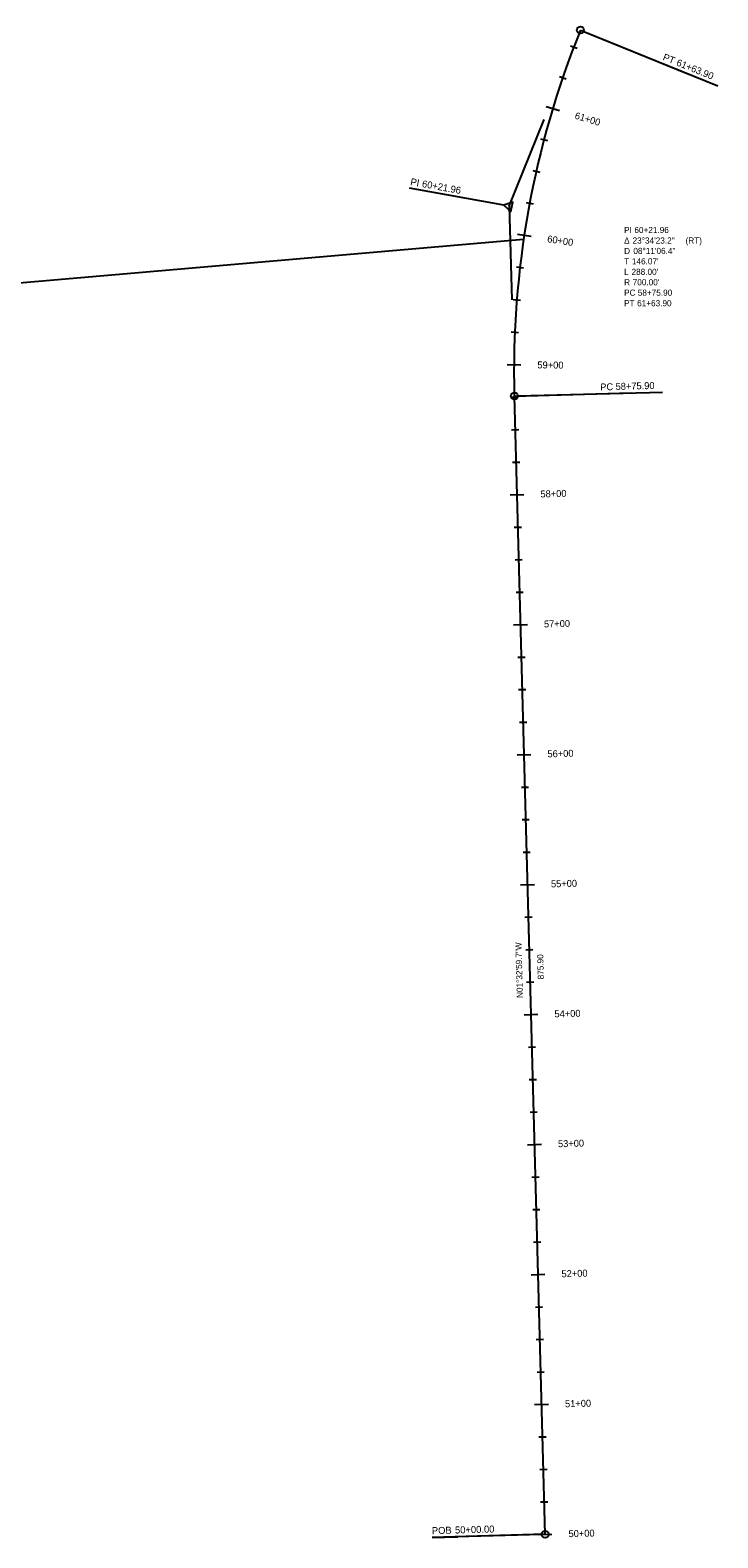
# Model space of a CAD drawing. Extents: x 2307903 to 2339201, y 758183 to 762824.
# Drawn here: x 2320206 to 2320735, y 758183 to 759343 of the extents above; entities that cross this region are included whole.
import ezdxf

# ---------------------------------------------------------------- set-up
doc = ezdxf.new("R2010")
doc.units = 0
for name, color, linetype in [('Default', 7, 'Continuous'), ('E_Terrain_Contour_Imported', 7, 'Continuous'), ('E_Terrain_Contour_Major', 7, 'Continuous'), ('E_Terrain_Flow_Arrows', 7, 'Continuous'), ('E_Terrain_Island', 7, 'Continuous'), ('E_Terrain_Points_High', 7, 'Continuous'), ('E_Terrain_Points_Low', 7, 'Continuous'), ('E_Terrain_SpotElevation', 7, 'Continuous'), ('Geom_Baseline', 7, 'Continuous')]:
    doc.layers.add(name, color=color, linetype=linetype)

msp = doc.modelspace()

# ---------------------------------------------------------------- linework, layer by layer
at = {"layer": 'Default'}
for p, q in [((2320621.7, 759331.1), (2320626.9, 759329.1)), ((2320613.2, 759307.5), (2320618.4, 759305.7)), ((2320603.1, 759284.4), (2320613.2, 759281.3)), ((2320598.7, 759259.5), (2320604, 759258.1)), ((2320592.8, 759235.1), (2320598.1, 759233.9)), ((2320587.7, 759210.5), (2320593.1, 759209.5)), ((2320580.9, 759186.1), (2320591.4, 759184.6)), ((2320580.2, 759160.9), (2320585.6, 759160.3)), ((2320577.7, 759135.9), (2320583.2, 759135.5)), ((2320576.2, 759110.9), (2320581.7, 759110.6)), ((2320573, 759085.8), (2320583.6, 759085.7)), ((2320602.3, 758186.1), (2320578.6, 759061.6)), ((2320602.3, 758186.1), (2320578.6, 759061.6)), ((2320602.3, 758186.1), (2320578.6, 759061.6)), ((2320602.3, 758186.1), (2320578.6, 759061.6)), ((2320575.8, 759060.7), (2320581.4, 759060.8)), ((2320576.5, 759035.7), (2320582, 759035.8)), ((2320577.2, 759010.7), (2320582.7, 759010.8)), ((2320575.3, 758985.6), (2320585.9, 758985.9)), ((2320578.5, 758960.7), (2320584.1, 758960.9)), ((2320579.2, 758935.7), (2320584.7, 758935.9)), ((2320579.9, 758910.7), (2320585.4, 758910.9)), ((2320578, 758885.7), (2320588.6, 758886)), ((2320581.2, 758860.7), (2320586.8, 758860.9)), ((2320581.9, 758835.8), (2320587.4, 758835.9)), ((2320582.6, 758810.8), (2320588.1, 758810.9)), ((2320580.7, 758785.7), (2320591.3, 758786)), ((2320584, 758760.8), (2320589.5, 758760.9)), ((2320584.6, 758735.8), (2320590.1, 758735.9)), ((2320585.3, 758710.8), (2320590.8, 758710.9)), ((2320583.4, 758685.7), (2320594, 758686)), ((2320586.7, 758660.8), (2320592.2, 758661)), ((2320587.3, 758635.8), (2320592.9, 758636)), ((2320588, 758610.8), (2320593.5, 758611)), ((2320586.1, 758585.8), (2320596.7, 758586.1)), ((2320589.4, 758560.9), (2320594.9, 758561)), ((2320590, 758535.9), (2320595.6, 758536)), ((2320590.7, 758510.9), (2320596.2, 758511)), ((2320588.8, 758485.8), (2320599.4, 758486.1)), ((2320592.1, 758460.9), (2320597.6, 758461)), ((2320592.7, 758435.9), (2320598.3, 758436)), ((2320593.4, 758410.9), (2320598.9, 758411.1)), ((2320591.5, 758385.8), (2320602.1, 758386.1)), ((2320594.8, 758360.9), (2320600.3, 758361.1)), ((2320595.4, 758335.9), (2320601, 758336.1)), ((2320596.1, 758310.9), (2320601.6, 758311.1)), ((2320594.2, 758285.9), (2320604.8, 758286.2)), ((2320597.5, 758261), (2320603, 758261.1)), ((2320598.2, 758236), (2320603.7, 758236.1)), ((2320598.8, 758211), (2320604.3, 758211.1)), ((2320596.9, 758185.9), (2320607.5, 758186.2))]:
    msp.add_line(p, q, dxfattribs=at)
msp.add_arc((2321278.3, 759080.6), 700, 157.9768, 181.5499, dxfattribs=at)
msp.add_arc((2321278.3, 759080.6), 700, 157.9768, 181.5499, dxfattribs=at)
msp.add_arc((2321278.3, 759080.6), 700, 157.9768, 181.5499, dxfattribs=at)
msp.add_arc((2321278.3, 759080.6), 700, 157.9768, 181.5499, dxfattribs=at)
msp.add_arc((2321278.3, 759080.6), 700, 157.9768, 181.5499, dxfattribs=at)
at = {"layer": 'E_Terrain_Contour_Imported'}
for p, q in [((2320621.7, 759331.1), (2320626.9, 759329.1)), ((2320613.2, 759307.5), (2320618.4, 759305.7)), ((2320598.7, 759259.5), (2320604, 759258.1)), ((2320592.8, 759235.1), (2320598.1, 759233.9)), ((2320587.7, 759210.5), (2320593.1, 759209.5)), ((2320580.2, 759160.9), (2320585.6, 759160.3)), ((2320577.7, 759135.9), (2320583.2, 759135.5)), ((2320576.2, 759110.9), (2320581.7, 759110.6)), ((2320575.8, 759060.7), (2320581.4, 759060.8)), ((2320576.5, 759035.7), (2320582, 759035.8)), ((2320577.2, 759010.7), (2320582.7, 759010.8)), ((2320578.5, 758960.7), (2320584.1, 758960.9)), ((2320579.2, 758935.7), (2320584.7, 758935.9)), ((2320579.9, 758910.7), (2320585.4, 758910.9)), ((2320581.2, 758860.7), (2320586.8, 758860.9)), ((2320581.9, 758835.8), (2320587.4, 758835.9)), ((2320582.6, 758810.8), (2320588.1, 758810.9)), ((2320584, 758760.8), (2320589.5, 758760.9)), ((2320584.6, 758735.8), (2320590.1, 758735.9)), ((2320585.3, 758710.8), (2320590.8, 758710.9)), ((2320586.7, 758660.8), (2320592.2, 758661)), ((2320587.3, 758635.8), (2320592.9, 758636)), ((2320588, 758610.8), (2320593.5, 758611)), ((2320589.4, 758560.9), (2320594.9, 758561)), ((2320590, 758535.9), (2320595.6, 758536)), ((2320590.7, 758510.9), (2320596.2, 758511)), ((2320592.1, 758460.9), (2320597.6, 758461)), ((2320592.7, 758435.9), (2320598.3, 758436)), ((2320593.4, 758410.9), (2320598.9, 758411.1)), ((2320594.8, 758360.9), (2320600.3, 758361.1)), ((2320595.4, 758335.9), (2320601, 758336.1)), ((2320596.1, 758310.9), (2320601.6, 758311.1)), ((2320597.5, 758261), (2320603, 758261.1)), ((2320598.2, 758236), (2320603.7, 758236.1)), ((2320598.8, 758211), (2320604.3, 758211.1))]:
    msp.add_line(p, q, dxfattribs=at)
at = {"layer": 'E_Terrain_Island'}
for p, q in [((2320603.1, 759284.4), (2320613.2, 759281.3)), ((2320580.9, 759186.1), (2320591.4, 759184.6)), ((2320573, 759085.8), (2320583.6, 759085.7)), ((2320575.3, 758985.6), (2320585.9, 758985.9)), ((2320578, 758885.7), (2320588.6, 758886)), ((2320580.7, 758785.7), (2320591.3, 758786)), ((2320583.4, 758685.7), (2320594, 758686)), ((2320586.1, 758585.8), (2320596.7, 758586.1)), ((2320588.8, 758485.8), (2320599.4, 758486.1)), ((2320591.5, 758385.8), (2320602.1, 758386.1)), ((2320594.2, 758285.9), (2320604.8, 758286.2)), ((2320596.9, 758185.9), (2320607.5, 758186.2))]:
    msp.add_line(p, q, dxfattribs=at)
at = {"layer": 'E_Terrain_Points_High'}
for p, q in [((2320631.9, 759342.1), (2320735.1, 759300.3)), ((2320574.6, 759207.7), (2320601.6, 759274.4)), ((2320570.5, 759208.4), (2320497.9, 759221.5)), ((2320574.6, 759207.7), (2320574.6, 759207.7)), ((2320574.6, 759207.7), (2320576.6, 759135.7)), ((2320581.2, 759061.7), (2320692.5, 759064.7))]:
    msp.add_line(p, q, dxfattribs=at)
msp.add_lwpolyline([(2320570.5, 759208.4), (2320576, 759203.7), (2320577.3, 759210.8)], close=True, dxfattribs=at)
msp.add_lwpolyline([(2320570.5, 759208.4), (2320576, 759203.7), (2320577.3, 759210.8)], close=True, dxfattribs=at)
at = {"layer": 'E_Terrain_SpotElevation'}
for p, q in [((2320629.4, 759343.1), (2320712.8, 759309.3)), ((2320735.1, 759300.3), (2320735.1, 759300.3)), ((2320497.9, 759221.5), (2320497.9, 759221.5)), ((2320574.6, 759207.7), (2320574.6, 759207.7)), ((2320578.6, 759061.6), (2320668.5, 759064.1)), ((2320578.6, 759061.6), (2320578.6, 759061.6)), ((2320692.5, 759064.7), (2320692.5, 759064.7)), ((2320602.3, 758186.1), (2320515.3, 758183.7)), ((2320599.6, 758186), (2320515.3, 758183.7)), ((2320515.3, 758183.7), (2320535, 758184.2)), ((2320602.3, 758186.1), (2320602.3, 758186.1))]:
    msp.add_line(p, q, dxfattribs=at)
for centre in [(2320629.4, 759343.1), (2320629.4, 759343.1), (2320578.6, 759061.6), (2320578.6, 759061.6), (2320602.3, 758186.1), (2320602.3, 758186.1)]:
    msp.add_circle(centre, 2.67, dxfattribs=at)
at = {"layer": 'Geom_Baseline'}
for p, q in [((2319888, 759122.1), (2320585.7, 759182.2)), ((2320602.3, 758186.1), (2320578.6, 759061.6))]:
    msp.add_line(p, q, dxfattribs=at)
msp.add_arc((2321278.3, 759080.6), 700, 157.9768, 181.5499, dxfattribs=at)

# ---------------------------------------------------------------- texts
at = {"layer": 'E_Terrain_Contour_Major'}
for s, rotation, p in [('61+00', 343.2069, (2320624.6, 759275.1)), ('60+00', 351.392, (2320603.6, 759180)), ('59+00', 359.5771, (2320596.3, 759082.9)), ('58+00', 1.5499, (2320598.7, 758983.6)), ('57+00', 1.5499, (2320601.4, 758883.6)), ('56+00', 1.5499, (2320604.1, 758783.7)), ('55+00', 1.5499, (2320606.8, 758683.7)), ('54+00', 1.5499, (2320609.5, 758583.7)), ('53+00', 1.5499, (2320612.2, 758483.8)), ('52+00', 1.5499, (2320614.9, 758383.8)), ('51+00', 1.5499, (2320617.6, 758283.8)), ('50+00', 1.5499, (2320620.3, 758183.9))]:
    msp.add_text(s, height=5.34, rotation=rotation, dxfattribs=at).set_placement(p)
at = {"layer": 'E_Terrain_Flow_Arrows'}
for s, height, p in [('N01°32\'59.7"W', 4.724, (2320585.2, 758598.7)), ('875.90', 4.72, (2320601.3, 758613))]:
    msp.add_text(s, height=height, rotation=91.5499, dxfattribs=at).set_placement(p)
at = {"layer": 'E_Terrain_Points_Low'}
for s, height, p in [('PI ', 4.72, (2320663, 759187)), ('60+21.96', 4.72, (2320670.9, 759187)), ('Δ ', 4.72, (2320663, 759178.9)), ('23°34\'23.2"', 4.724, (2320669.5, 759178.9)), (' (RT)', 4.72, (2320708.5, 759178.9)), ('T ', 4.72, (2320663, 759162.9)), ('D ', 4.72, (2320663, 759170.9)), ("146.07'", 4.72, (2320669, 759162.9)), ('08°11\'06.4"', 4.724, (2320670.1, 759170.9)), ('L ', 4.72, (2320663, 759154.8)), ("288.00'", 4.72, (2320668.7, 759154.8)), ('R ', 4.72, (2320663, 759146.8)), ('PC ', 4.72, (2320663, 759138.8)), ("700.00'", 4.72, (2320669.6, 759146.8)), ('58+75.90', 4.72, (2320673.5, 759138.8)), ('PT ', 4.72, (2320663, 759130.7)), ('61+63.90', 4.72, (2320673, 759130.7))]:
    msp.add_text(s, height=height, dxfattribs=at).set_placement(p)
at = {"layer": 'E_Terrain_SpotElevation'}
for s, height, rotation, p in [('PT', 5.34, 337.9768, (2320692.3, 759320.3)), ('61+63.90', 5.34, 337.9768, (2320702.7, 759316.1)), ('PI ', 5.4, 349.7634, (2320498.3, 759224)), ('60+21.96', 5.4, 349.7634, (2320507.2, 759222.4)), ('PC', 5.34, 1.5499, (2320644.7, 759065.9)), ('58+75.90', 5.34, 1.5499, (2320656.5, 759066.3)), ('POB ', 5.4, 1.5499, (2320515.2, 758186.2)), ('50+00.00', 5.4, 1.5499, (2320533, 758186.7))]:
    msp.add_text(s, height=height, rotation=rotation, dxfattribs=at).set_placement(p)

doc.saveas('drawing.dxf')
